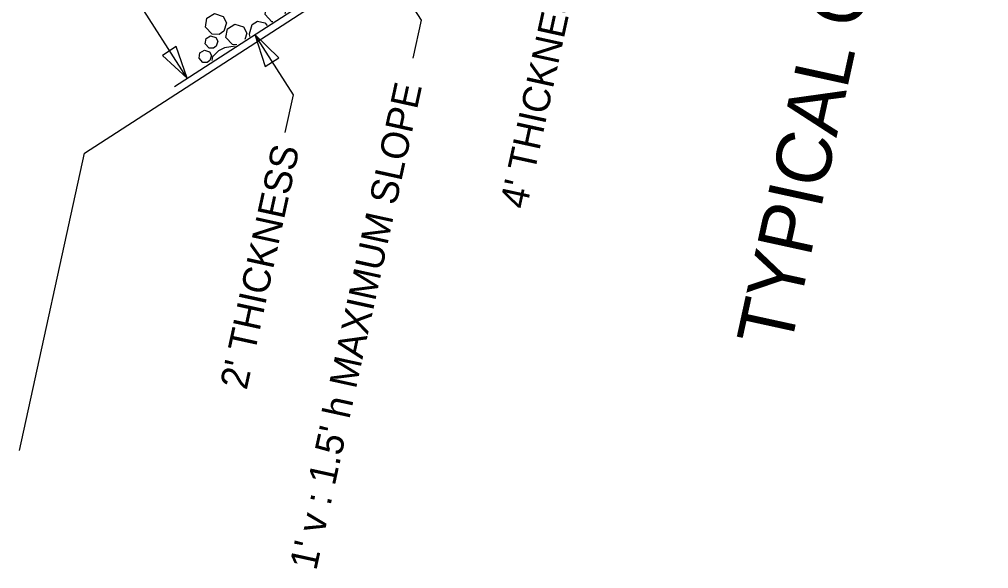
# Model space of a CAD drawing. Extents: x 2126110 to 2128246, y 1804858 to 1811658.
# Drawn here: x 2126528.5 to 2126704.7, y 1804858.4 to 1804958.2 of the extents above; entities that cross this region are included whole.
import ezdxf

# ---------------------------------------------------------------- set-up
doc = ezdxf.new("R2010")
doc.units = 0
doc.layers.add('1', color=7, linetype='Continuous')
doc.layers.add('Old_Level_1', color=7, linetype='Continuous')

msp = doc.modelspace()

# ---------------------------------------------------------------- linework, layer by layer
at = {"layer": '1'}
for p, q in [((2126540.29, 1804933.93), (2126635.66, 1804995.49)), ((2126556.68, 1804946.03), (2126634.52, 1804996.26)), ((2126559.01, 1804947.53), (2126530.17, 1804992.45)), ((2126601.6, 1804958.05), (2126594.59, 1804968.98)), ((2126574.54, 1804957.79), (2126574.36, 1804957.8)), ((2126600.1, 1804951.16), (2126601.6, 1804958.05)), ((2126578.3, 1804944.53), (2126571.29, 1804955.46)), ((2126565.75, 1804953.08), (2126567.69, 1804953.4)), ((2126568.03, 1804953.62), (2126567.23, 1804953.63)), ((2126576.8, 1804937.64), (2126578.3, 1804944.53)), ((2126528.48, 1804879.88), (2126540.29, 1804933.93))]:
    msp.add_line(p, q, dxfattribs=at)
for points in [[(2126574.36, 1804957.8), (2126573.18, 1804959.09), (2126573.43, 1804960.68), (2126574.8, 1804961.53), (2126576.36, 1804961.02), (2126576.95, 1804959.87), (2126576.76, 1804959.22)], [(2126563.53, 1804955.53), (2126562.34, 1804956.82), (2126562.59, 1804958.41), (2126563.97, 1804959.26), (2126565.52, 1804958.75), (2126566.12, 1804957.61), (2126565.67, 1804956.08), (2126564.8, 1804955.5), (2126563.53, 1804955.53)], [(2126570.39, 1804955.13), (2126570.31, 1804955.61), (2126570.83, 1804957.27), (2126571.77, 1804957.91), (2126573.14, 1804957.59), (2126573.51, 1804957.13)], [(2126567.23, 1804953.63), (2126566.04, 1804954.93), (2126566.3, 1804956.52), (2126567.67, 1804957.36), (2126569.23, 1804956.86), (2126569.82, 1804955.71), (2126569.48, 1804954.55)], [(2126562.99, 1804953), (2126562.28, 1804953.77), (2126562.43, 1804954.73), (2126563.25, 1804955.24), (2126564.19, 1804954.93), (2126564.54, 1804954.24), (2126564.27, 1804953.33), (2126563.75, 1804952.98), (2126562.99, 1804953)], [(2126561.86, 1804950.39), (2126561.15, 1804951.16), (2126561.3, 1804952.12), (2126562.12, 1804952.62), (2126563.05, 1804952.32), (2126563.41, 1804951.63), (2126563.14, 1804950.72), (2126562.62, 1804950.37), (2126561.86, 1804950.39)], [(2126563.54, 1804950.74), (2126563.65, 1804951.48), (2126564.74, 1804952.57), (2126565.84, 1804953.11)]]:
    msp.add_lwpolyline(points, dxfattribs=at)
for points in [[(2126575.66, 1804951.22), (2126571.29, 1804955.46), (2126573.15, 1804949.66)], [(2126554.52, 1804951.65), (2126559.01, 1804947.53), (2126556.98, 1804953.28)]]:
    msp.add_lwpolyline(points, close=True, dxfattribs=at)

# ---------------------------------------------------------------- texts
for s, p in [("4' THICKNESS", (2126620.68, 1804923.55)), ("1' v : 1.5' h MAXIMUM SLOPE", (2126582.45, 1804857.9)), ("2' THICKNESS", (2126569.8, 1804890.72))]:
    msp.add_text(s, height=5, rotation=77.6736, dxfattribs=at).set_placement(p)
at = {"layer": 'Old_Level_1'}
msp.add_text('TYPICAL CROSS SECTION', height=10, rotation=77.6737, dxfattribs=at).set_placement((2126668.64, 1804898.14))

doc.saveas('drawing.dxf')
